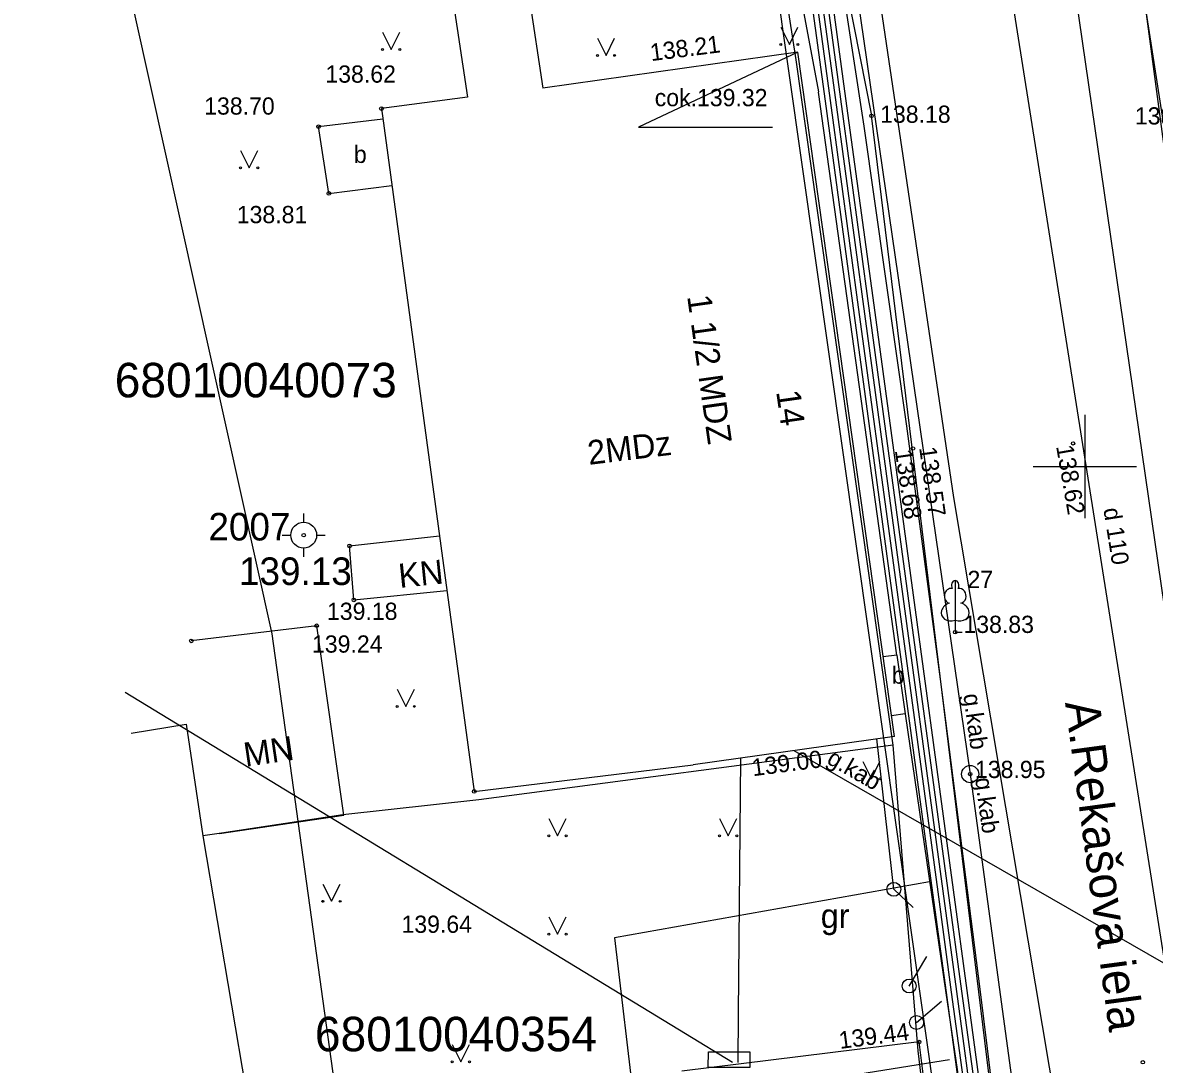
# Model space of a CAD drawing. Extents: x 728710 to 728960, y 272811 to 273475.
# Drawn here: x 728769.2 to 728802.02, y 273232.66 to 273262.88 of the extents above; entities that cross this region are included whole.
import ezdxf

# ---------------------------------------------------------------- set-up
doc = ezdxf.new("R2010")
doc.units = 0
for name, color, linetype in [('Level 10', 7, 'Continuous'), ('Level 15', 7, 'Continuous'), ('Level 16', 7, 'Continuous'), ('Level 17', 7, 'Continuous'), ('Level 21', 7, 'Continuous'), ('Level 23', 7, 'Continuous'), ('Level 27', 7, 'Continuous'), ('Level 3', 7, 'Continuous'), ('Level 4', 7, 'Continuous'), ('Level 41', 7, 'Continuous'), ('Level 42', 7, 'Continuous'), ('Level 43', 7, 'Continuous'), ('Level 48', 7, 'Continuous'), ('Level 50', 7, 'Continuous'), ('Level 53', 7, 'Continuous'), ('Level 54', 7, 'Continuous'), ('Level 55', 7, 'Continuous'), ('Level 57', 7, 'Continuous'), ('Level 58', 7, 'Continuous'), ('Level 59', 7, 'Continuous'), ('Level 62', 7, 'Continuous'), ('Level 63', 7, 'Continuous'), ('Level 9', 7, 'Continuous'), ('RAMI_UZMR_####_####_#', 7, 'Continuous'), ('RELJ_NOGA_####_####_#', 7, 'Continuous'), ('ROBZ_ELEM_####_####_#', 7, 'Continuous'), ('ROBZ_KADS_####_TKST_#', 7, 'Continuous'), ('ROBZ_UZMR_####_####_#', 7, 'Continuous'), ('SAKT_VADV_PKAB_TKST_#', 7, 'Continuous'), ('TERT_KONT_####_####_#', 7, 'Continuous')]:
    doc.layers.add(name, color=color, linetype=linetype)

msp = doc.modelspace()

# ---------------------------------------------------------------- linework, layer by layer
at = {"layer": 'Level 10'}
for p, q in [((728800, 273251.5), (728800, 273250)), ((728798.5, 273250), (728800, 273250)), ((728800, 273250), (728800, 273248.5)), ((728800, 273250), (728801.5, 273250)), ((728777.346, 273248.385), (728777.346, 273248.635)), ((728776.721, 273248.01), (728776.971, 273248.01)), ((728777.721, 273248.01), (728777.971, 273248.01)), ((728777.346, 273247.385), (728777.346, 273247.635))]:
    msp.add_line(p, q, dxfattribs=at)
for radius in [0.375, 0.05]:
    msp.add_circle((728777.346, 273248.01), radius, dxfattribs=at)
at = {"layer": 'Level 15'}
msp.add_lwpolyline([(728789.081, 273233.019), (728790.282, 273233.019), (728790.281, 273232.568), (728789.08, 273232.568)], close=True, dxfattribs=at)
msp.add_circle((728796.674, 273241.078), 0.25, dxfattribs=at)
at = {"layer": 'Level 16'}
for p, q in [((728788.42, 273233.543), (728772.167, 273243.444)), ((728789.96, 273234.137), (728790.028, 273241.535)), ((728789.947, 273232.711), (728789.96, 273234.137)), ((728789.786, 273232.711), (728788.42, 273233.543))]:
    msp.add_line(p, q, dxfattribs=at)
for points in [[(728796.584, 273234.798), (728796.188, 273237.718), (728794.844, 273247.623), (728793.915, 273254.468), (728793.072, 273260.678), (728792.237, 273266.832), (728792.018, 273268.442), (728791.441, 273269.339), (728790.859, 273269.531), (728790.317, 273269.458), (728789.54, 273268.992), (728788.888, 273268.365), (728788.207, 273268.098), (728788.13, 273268.116), (728788.048, 273268.244), (728787.945, 273268.914), (728787.922, 273269.074)], [(728796.286, 273234.768), (728795.891, 273237.678), (728794.547, 273247.583), (728793.618, 273254.428), (728792.775, 273260.638), (728791.94, 273266.792), (728791.73, 273268.336), (728791.246, 273269.088), (728790.831, 273269.225), (728790.418, 273269.169), (728789.723, 273268.752), (728789.053, 273268.108), (728788.229, 273267.785), (728787.943, 273267.852), (728787.761, 273268.136), (728787.648, 273268.871), (728787.626, 273269.033)], [(728796.436, 273234.783), (728796.04, 273237.698), (728794.696, 273247.603), (728793.767, 273254.448), (728792.924, 273260.658), (728792.088, 273266.812), (728791.874, 273268.389), (728791.343, 273269.214), (728790.845, 273269.378), (728790.367, 273269.314), (728789.631, 273268.872), (728788.971, 273268.237), (728788.218, 273267.942), (728788.036, 273267.984), (728787.904, 273268.19), (728787.796, 273268.893), (728787.774, 273269.053)], [(728795.987, 273234.738), (728795.594, 273237.638), (728794.25, 273247.542), (728793.321, 273254.387), (728792.478, 273260.597), (728791.642, 273266.752), (728791.442, 273268.23), (728791.051, 273268.836), (728790.803, 273268.918), (728790.519, 273268.88), (728789.907, 273268.512), (728789.218, 273267.85), (728788.252, 273267.471), (728787.756, 273267.588), (728787.474, 273268.028), (728787.351, 273268.828), (728787.328, 273268.991)], [(728796.136, 273234.753), (728795.742, 273237.658), (728794.398, 273247.562), (728793.468, 273254.408), (728792.626, 273260.617), (728791.79, 273266.772), (728791.585, 273268.282), (728791.148, 273268.961), (728790.817, 273269.071), (728790.469, 273269.024), (728789.815, 273268.631), (728789.136, 273267.978), (728788.24, 273267.627), (728787.849, 273267.719), (728787.617, 273268.081), (728787.499, 273268.849), (728787.476, 273269.012)], [(728790.477, 273216.013), (728797.041, 273217.017), (728797.486, 273217.085), (728797.777, 273217.408), (728798.493, 273218.343), (728798.042, 273221.829), (728797.325, 273227.119), (728796.821, 273230.824), (728796.286, 273234.768)], [(728797.417, 273219.529), (728797.598, 273219.748), (728797.897, 273220.614), (728797.745, 273221.789), (728797.027, 273227.078), (728796.524, 273230.784), (728795.987, 273234.738)], [(728797.509, 273219.41), (728797.731, 273219.674), (728798.049, 273220.599), (728797.893, 273221.809), (728797.175, 273227.098), (728796.672, 273230.804), (728796.136, 273234.753)], [(728798.647, 273218.321), (728798.191, 273221.849), (728797.473, 273227.139), (728796.97, 273230.845), (728796.436, 273234.783)], [(728798.795, 273218.34), (728798.339, 273221.868), (728797.621, 273227.159), (728797.118, 273230.865), (728796.584, 273234.798)]]:
    msp.add_lwpolyline(points, dxfattribs=at)
at = {"layer": 'Level 17'}
msp.add_lwpolyline([(728797.092, 273268.609), (728802.352, 273235.373)], dxfattribs=at)
at = {"layer": 'Level 21'}
for p, q in [((728791.151, 273279.124), (728796.674, 273241.078)), ((728796.674, 273241.078), (728799.963, 273216.945))]:
    msp.add_line(p, q, dxfattribs=at)
at = {"layer": 'Level 23'}
msp.add_line((728799.123, 273267.839), (728803.964, 273234.42), dxfattribs=at)
at = {"layer": 'Level 27'}
msp.add_lwpolyline([(728794.46, 273237.735), (728793.966, 273242.101)], dxfattribs=at)
at = {"layer": 'Level 3'}
for p, q in [((728783.825, 273264.036), (728784.278, 273260.982)), ((728781.655, 273263.689), (728782.101, 273260.719)), ((728791.672, 273262.027), (728784.278, 273260.982)), ((728794.476, 273242.173), (728791.672, 273262.027)), ((728782.101, 273260.719), (728779.602, 273260.386)), ((728779.602, 273260.386), (728782.292, 273240.575)), ((728778.676, 273247.7), (728781.284, 273247.995)), ((728778.802, 273246.132), (728778.676, 273247.7)), ((728778.802, 273246.132), (728781.5, 273246.407)), ((728777.723, 273245.384), (728774.087, 273244.944)), ((728778.513, 273239.884), (728777.723, 273245.384)), ((728794.476, 273242.173), (728788.643, 273241.349)), ((728782.292, 273240.575), (728788.643, 273241.349)), ((728774.9, 273239.354), (728778.513, 273239.884)), ((728795.197, 273233.307), (728788.317, 273232.464)), ((728797.066, 273218.061), (728795.197, 273233.307))]:
    msp.add_line(p, q, dxfattribs=at)
at = {"layer": 'Level 4'}
for p, q in [((728792.392, 273267.41), (728793.815, 273260.182)), ((728794.546, 273244.533), (728792.28, 273260.864)), ((728797.287, 273231.807), (728793.815, 273260.182)), ((728794.787, 273242.827), (728795.97, 273234.736)), ((728795.97, 273234.736), (728797.349, 273225.3))]:
    msp.add_line(p, q, dxfattribs=at)
for points in [[(728803.413, 273250.931), (728800.916, 273269.685), (728796.563, 273300.793)], [(728792.281, 273260.872), (728791.163, 273266.868), (728790.618, 273271.155)], [(728795.499, 273237.956), (728786.359, 273236.325), (728786.949, 273231.342), (728796.072, 273232.795)]]:
    msp.add_lwpolyline(points, dxfattribs=at)
at = {"layer": 'Level 41'}
msp.add_lwpolyline([(728806.045, 273235.742), (728805.58, 273238.737), (728804.235, 273247.399), (728800.223, 273273.247), (728790.96, 273338.691), (728788.283, 273357.608), (728788.02, 273359.462)], dxfattribs=at)
at = {"layer": 'Level 42'}
for points in [[(728798.57, 273234.996), (728796.2, 273249.103), (728793.53, 273267.106), (728793.316, 273268.554), (728792.523, 273271.435), (728791.689, 273271.885), (728791.331, 273271.857), (728790.525, 273271.316), (728790.114, 273271.031), (728790.098, 273270.001), (728790.066, 273268.036), (728789.16, 273266.899), (728788.854, 273266.581), (728787.526, 273266.207), (728786.731, 273266.132), (728785.171, 273266.735), (728784.508, 273267.612), (728784.237, 273267.971), (728784.229, 273269.186), (728784.655, 273269.719), (728785.153, 273269.759)], [(728792.261, 273268.58), (728793.589, 273259.881), (728794.83, 273251.169), (728795.808, 273243.834), (728796.953, 273234.834)], [(728790.816, 273213.839), (728798.005, 273214.912), (728800.599, 273216.119), (728801.262, 273217.688), (728799.779, 273227.802), (728798.57, 273234.996)], [(728796.953, 273234.834), (728797.171, 273233.12), (728798.705, 273220.412), (728798.759, 273219.965), (728799.063, 273219.076), (728799.29, 273218.573), (728800.035, 273218.111), (728802.6, 273218.3), (728805.991, 273218.55), (728811.368, 273219.028), (728821.256, 273220.241)]]:
    msp.add_lwpolyline(points, dxfattribs=at)
at = {"layer": 'Level 43'}
for p, q in [((728794.46, 273237.735), (728795.021, 273237.206)), ((728794.906, 273234.93), (728795.417, 273235.789)), ((728795.12, 273233.871), (728795.838, 273234.491))]:
    msp.add_line(p, q, dxfattribs=at)
for centre in [(728794.46, 273237.735), (728794.906, 273234.93), (728795.12, 273233.871)]:
    msp.add_circle(centre, 0.202, dxfattribs=at)
at = {"layer": 'Level 48'}
for centre, radius in [((728779.602, 273260.386), 0.0534), ((728793.813, 273260.175), 0.05), ((728777.777, 273259.862), 0.0534), ((728778.078, 273257.926), 0.0534), ((728795.015, 273250.525), 0.05), ((728799.658, 273250.672), 0.05), ((728778.676, 273247.7), 0.0534), ((728778.802, 273246.132), 0.0534), ((728777.723, 273245.384), 0.0534), ((728796.24, 273245.195), 0.05), ((728774.087, 273244.944), 0.0534), ((728796.674, 273241.078), 0.05), ((728782.292, 273240.575), 0.0534), ((728795.197, 273233.307), 0.05), ((728801.68, 273232.719), 0.05)]:
    msp.add_circle(centre, radius, dxfattribs=at)
at = {"layer": 'Level 9'}
for p, q in [((728777.777, 273259.862), (728779.643, 273260.085)), ((728778.078, 273257.926), (728777.777, 273259.862)), ((728778.078, 273257.926), (728779.905, 273258.153)), ((728794.546, 273244.533), (728794.151, 273244.477)), ((728794.546, 273244.533), (728794.787, 273242.827)), ((728794.787, 273242.827), (728794.391, 273242.772))]:
    msp.add_line(p, q, dxfattribs=at)
msp.add_lwpolyline([(728791.672, 273262.027), (728787.056, 273259.852), (728790.943, 273259.852)], dxfattribs=at)
at = {"layer": 'RAMI_UZMR_####_####_#'}
for points in [[(728776.746, 273299.712), (728774.767, 273288.109), (728769.195, 273286.654), (728770.672, 273271.11), (728776.42, 273245.146), (728778.568, 273229.68), (728773.046, 273228.469), (728773.87, 273214.498), (728774.426, 273201.627), (728776.99, 273195.753), (728795.127, 273200.451), (728799.264, 273172.386), (728794.758, 273166.22), (728789.327, 273163.194), (728788.892, 273161.497), (728790.999, 273149.932)], [(728791.56, 273241.761), (728823.339, 273223.506)]]:
    msp.add_lwpolyline(points, dxfattribs=at)
at = {"layer": 'ROBZ_ELEM_####_####_#'}
msp.add_lwpolyline([(728797.679, 273217.456), (728777.701, 273357.893)], dxfattribs=at)
at = {"layer": 'ROBZ_UZMR_####_####_#'}
for p, q in [((728791.63, 273261.802), (728790.169, 273271.078)), ((728794.442, 273241.916), (728791.63, 273261.802)), ((728772.341, 273242.261), (728773.94, 273242.524)), ((728773.94, 273242.524), (728774.418, 273239.286)), ((728794.442, 273241.916), (728782.427, 273240.328)), ((728795.166, 273233.048), (728794.442, 273241.916)), ((728782.427, 273240.328), (728778.484, 273239.899)), ((728778.484, 273239.899), (728774.967, 273239.362)), ((728774.967, 273239.362), (728774.418, 273239.286)), ((728774.418, 273239.286), (728776.461, 273227.298)), ((728797.009, 273217.805), (728795.166, 273233.048))]:
    msp.add_line(p, q, dxfattribs=at)
at = {"layer": 'TERT_KONT_####_####_#'}
for p, q in [((728779.633, 273262.601), (728779.883, 273262.101)), ((728779.883, 273262.101), (728780.133, 273262.601)), ((728791.18, 273262.744), (728791.43, 273262.244)), ((728791.43, 273262.244), (728791.68, 273262.744)), ((728785.864, 273262.429), (728786.114, 273261.929)), ((728786.114, 273261.929), (728786.364, 273262.429)), ((728775.517, 273259.168), (728775.767, 273258.668)), ((728775.767, 273258.668), (728776.017, 273259.168)), ((728796.24, 273245.542), (728796.24, 273245.195)), ((728796.24, 273245.195), (728796.44, 273245.195)), ((728780.055, 273243.543), (728780.305, 273243.043)), ((728780.305, 273243.043), (728780.555, 273243.543)), ((728793.559, 273241.441), (728793.809, 273240.941)), ((728793.809, 273240.941), (728794.059, 273241.441)), ((728784.456, 273239.789), (728784.706, 273239.289)), ((728784.706, 273239.289), (728784.956, 273239.789)), ((728789.408, 273239.789), (728789.658, 273239.289)), ((728789.658, 273239.289), (728789.908, 273239.789)), ((728777.904, 273237.887), (728778.154, 273237.387)), ((728778.154, 273237.387), (728778.404, 273237.887)), ((728784.456, 273236.936), (728784.706, 273236.436)), ((728784.706, 273236.436), (728784.956, 273236.936)), ((728781.655, 273233.232), (728781.905, 273232.732)), ((728781.905, 273232.732), (728782.155, 273233.232))]:
    msp.add_line(p, q, dxfattribs=at)
for points in [[(728796.24, 273246.695), (728796.24, 273245.542)], [(728796.33, 273246.463), (728796.329, 273246.464)]]:
    msp.add_lwpolyline(points, dxfattribs=at)
for centre, radius in [((728791.179, 273262.244), 0.028), ((728791.679, 273262.244), 0.0263), ((728779.633, 273262.101), 0.028), ((728780.133, 273262.101), 0.0263), ((728785.863, 273261.929), 0.028), ((728786.363, 273261.929), 0.0263), ((728775.517, 273258.668), 0.028), ((728776.017, 273258.668), 0.0263), ((728780.054, 273243.043), 0.028), ((728780.554, 273243.043), 0.0263), ((728793.559, 273240.941), 0.028), ((728794.059, 273240.941), 0.0263), ((728784.456, 273239.289), 0.028), ((728784.956, 273239.289), 0.0263), ((728789.407, 273239.289), 0.028), ((728789.907, 273239.289), 0.0263), ((728777.904, 273237.387), 0.028), ((728778.404, 273237.387), 0.0263), ((728784.456, 273236.435), 0.028), ((728784.956, 273236.435), 0.0263), ((728781.655, 273232.731), 0.028), ((728782.155, 273232.731), 0.0263)]:
    msp.add_circle(centre, radius, dxfattribs=at)
for centre, major_axis, ratio, start_param, end_param in [((728796.24, 273246.545), (0, -0.15), 0.707107, 3.14537, 5.287485), ((728796.24, 273246.545), (0, -0.15), 0.707107, 0.995701, 3.137816), ((728796.112, 273246.25), (-0.039, -0.212), 0.861323, 3.141593, 6.283185), ((728796.368, 273246.25), (0.039, -0.212), 0.861323, 0, 3.141593), ((728796.15, 273245.788), (0.307, 0.095), 0.814445, 1.570796, 4.752015), ((728796.33, 273245.788), (-0.307, 0.095), 0.814445, 1.531171, 4.712389)]:
    msp.add_ellipse(centre, major_axis=major_axis, ratio=ratio, start_param=start_param, end_param=end_param, dxfattribs=at)

# ---------------------------------------------------------------- texts
at = {"layer": 'Level 50'}
for s, p in [('cok.139.32', (728787.526, 273260.455)), ('b', (728778.802, 273258.809)), ('b', (728794.401, 273243.701))]:
    msp.add_text(s, height=0.5, dxfattribs=at).set_placement(p)
at = {"layer": 'Level 53'}
for p in [(728796.472, 273243.383), (728796.812, 273240.949)]:
    msp.add_text('g.kab', height=0.5, rotation=277.761, dxfattribs=at).set_placement(p)
at = {"layer": 'Level 54'}
msp.add_text('A.Rekašova iela', height=1, rotation=277.641, dxfattribs=at).set_placement((728799.423, 273243.151))
at = {"layer": 'Level 55'}
msp.add_text('d 110', height=0.5, rotation=278.9929, dxfattribs=at).set_placement((728800.535, 273248.77))
at = {"layer": 'Level 57'}
for s, rotation, p in [(' 138.21', 7.2491, (728787.24, 273261.739)), ('138.68', 278.231, (728794.489, 273250.467)), ('138.57', 277.9955, (728795.194, 273250.546)), ('138.62', 279.8336, (728799.165, 273250.587)), (' 139.00', 7.4676, (728790.192, 273240.991)), (' 139.44', 7.4668, (728792.715, 273233.079))]:
    msp.add_text(s, height=0.5, rotation=rotation, dxfattribs=at).set_placement(p)
for s, p in [(' 138.62', (728777.79, 273261.138)), (' 138.70', (728774.274, 273260.211)), (' 138.18', (728793.877, 273259.973)), (' 138.27', (728801.265, 273259.925)), (' 138.81', (728775.219, 273257.062)), (' 139.18', (728777.836, 273245.552)), (' 138.83', (728796.293, 273245.173)), (' 139.24', (728777.401, 273244.602)), (' 138.95', (728796.628, 273240.964)), (' 139.64', (728779.996, 273236.473))]:
    msp.add_text(s, height=0.5, dxfattribs=at).set_placement(p)
at = {"layer": 'Level 58'}
msp.add_text('gr', height=0.7, dxfattribs=at).set_placement((728792.341, 273236.613))
at = {"layer": 'Level 59'}
for s, rotation, p in [('1 1/2 MDZ', 278.039, (728788.465, 273254.94)), ('2MDz', 6.9434, (728785.621, 273250.049)), ('KN', 5.8199, (728780.13, 273246.478)), ('MN', 8.3453, (728775.659, 273241.288))]:
    msp.add_text(s, height=0.7, rotation=rotation, dxfattribs=at).set_placement(p)
at = {"layer": 'Level 62'}
msp.add_text('14', height=0.7, rotation=278.039, dxfattribs=at).set_placement((728791.047, 273252.174))
at = {"layer": 'Level 63'}
for s, p in [(' 2007', (728774.286, 273247.856)), (' 139.13', (728775.172, 273246.564))]:
    msp.add_text(s, height=0.8, dxfattribs=at).set_placement(p)
at = {"layer": 'RELJ_NOGA_####_####_#'}
msp.add_text('27', height=0.5, dxfattribs=at).set_placement((728796.596, 273246.476))
at = {"layer": 'ROBZ_KADS_####_TKST_#'}
for s, p in [('68010040073', (728771.866, 273252.009)), ('68010040354', (728777.671, 273233.037))]:
    msp.add_text(s, height=1, dxfattribs=at).set_placement(p)
at = {"layer": 'SAKT_VADV_PKAB_TKST_#'}
msp.add_text('g.kab', height=0.5, rotation=330.1247, dxfattribs=at).set_placement((728792.483, 273241.403))

doc.saveas('drawing.dxf')
